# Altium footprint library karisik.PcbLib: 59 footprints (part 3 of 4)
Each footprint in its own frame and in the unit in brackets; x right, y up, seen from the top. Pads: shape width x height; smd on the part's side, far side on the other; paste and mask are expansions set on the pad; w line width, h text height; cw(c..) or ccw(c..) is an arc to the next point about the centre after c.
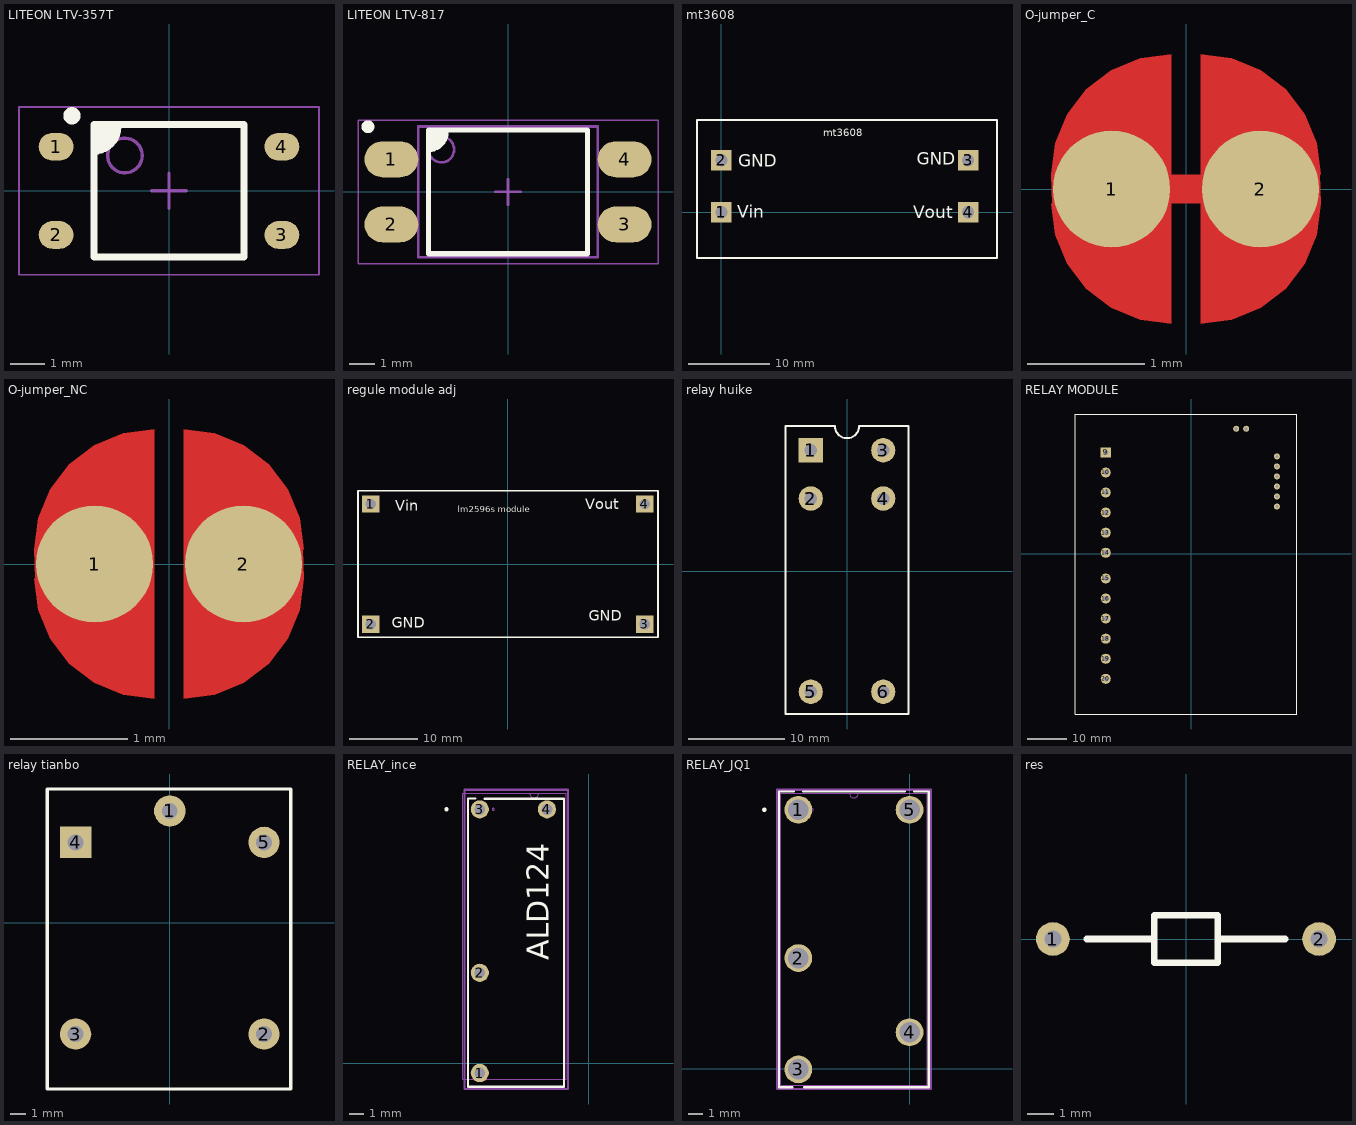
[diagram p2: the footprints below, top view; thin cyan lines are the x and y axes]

## LITEON LTV-357T [mm] "SOP, 4-Leads, Body 3.85x4.4mm, Pitch 2.54mm, IPC Medium Density"
height 2.1
pads (4):
  oval 1x0.8 smd: 1(-3.25,1.27) 2(-3.25,-1.27) 3(3.25,-1.27) 4(3.25,1.27)
Top Overlay:
  circle w0.25: c-2.794,2.159 r0.125
  region: -2.159,1.905 -1.472,1.905 -1.472,1.524 -1.853,1.143 -2.159,1.143
  lines w0.2: -2.159,1.143 ccw(c-2.159,1.83) -1.472,1.83 ; -2.159,-1.905 2.159,-1.905 2.159,1.905 -2.159,1.905 -2.159,-1.905
Mechanical 13:
  circle w0.1: c-1.27,1.016 r0.5
  lines w0.1: -2.159,-1.905 2.159,-1.905 2.159,1.905 -2.159,1.905 -2.159,-1.905
Mechanical 15:
  lines w0.05: -4.318,-2.413 4.318,-2.413 4.318,2.413 -4.318,2.413 -4.318,-2.413
  lines w0.1: -0.5,0 0.5,0 ; 0,-0.5 0,0.5
3D body: height 2.1, standoff 0, extent -3.514,-1.925 3.514,1.925

## LITEON LTV-817 [mm] "SOP, 4-Leads, Body 4.60x6.50mm, Pitch 2.54mm, IPC Medium Density"
height 4.35
pads (4):
  oval 2.1x1.4 smd: 1(-4.55,1.27) 2(-4.55,-1.27) 3(4.55,-1.27) 4(4.55,1.27)
Top Overlay:
  circle w0.25: c-5.461,2.54 r0.125
  region: -3.1,2.413 -2.413,2.413 -2.413,2.032 -2.794,1.651 -3.1,1.651
  lines w0.2: -3.1,1.651 ccw(c-3.1,2.338) -2.413,2.338 ; -3.1,-2.413 3.1,-2.413 3.1,2.413 -3.1,2.413 -3.1,-2.413
Mechanical 13:
  circle w0.1: c-2.6,1.65 r0.5
  lines w0.1: -3.5,-2.55 3.5,-2.55 3.5,2.55 -3.5,2.55 -3.5,-2.55
Mechanical 15:
  lines w0.05: -5.85,-2.8 5.85,-2.8 5.85,2.8 -5.85,2.8 -5.85,-2.8
  lines w0.1: -0.5,0 0.5,0 ; 0,-0.5 0,0.5
3D body: height 3.85, standoff 0, extent -5.098,-2.3 5.098,2.3

## mt3608 [mil] "ayarlý regulatör"
height 400
pads (4):
  rect 100x100 hole 60: 1(0,0) 2(0,253) 3(1201,253) 4(1201,0)
Top Overlay:
  lines w10: 1339,450 -119,450 -119,-224 1342,-224 1342,449
  text "Vout" at 934,-29 h60
  text "GND" at 951,231 h60
  text "GND" at 83,221 h60
  text "Vin" at 77,-26 h60
  text "mt3608" at 497,358 h60

## O-jumper_C [mm]
pads (2):
  round 1 smd paste-2: 1(-0.635,0) 2(0.635,0)
Top Layer:
  region: -0.127,-1.152 -0.392,-1.117 -0.639,-1.014 -0.852,-0.852 -1.014,-0.639 -1.117,-0.392 -1.152,-0.127 -1.143,-0.127 -1.152,0.127 -1.117,0.392 -1.014,0.639 -0.852,0.852 -0.639,1.014 -0.392,1.117 -0.127,1.152 -0.127,1.143
  region: 0.127,1.152 0.392,1.117 0.639,1.014 0.852,0.852 1.014,0.639 1.117,0.392 1.152,0.127 1.143,0.127 1.152,-0.127 1.117,-0.392 1.014,-0.639 0.852,-0.852 0.639,-1.014 0.392,-1.117 0.127,-1.152 0.127,-1.143
  lines w0.25: -0.635,0 0.635,0
Top Solder:
  region: 0,1.281 0.332,1.237 0.64,1.109 0.906,0.906 1.109,0.64 1.237,0.332 1.281,0 1.237,-0.332 1.109,-0.64 0.906,-0.906 0.64,-1.109 0.332,-1.237 0,-1.281 -0.332,-1.237 -0.64,-1.109 -0.906,-0.906 -1.109,-0.64 -1.237,-0.332 -1.281,0 -1.237,0.332 -1.109,0.64 -0.906,0.906 -0.64,1.109 -0.332,1.237

## O-jumper_NC [mm]
pads (2):
  round 1 smd paste-2: 1(-0.635,0) 2(0.635,0)
Top Layer:
  region: -0.127,-1.152 -0.392,-1.117 -0.639,-1.014 -0.852,-0.852 -1.014,-0.639 -1.117,-0.392 -1.152,-0.127 -1.143,-0.127 -1.152,0.127 -1.117,0.392 -1.014,0.639 -0.852,0.852 -0.639,1.014 -0.392,1.117 -0.127,1.152 -0.127,1.143
  region: 0.127,1.152 0.392,1.117 0.639,1.014 0.852,0.852 1.014,0.639 1.117,0.392 1.152,0.127 1.143,0.127 1.152,-0.127 1.117,-0.392 1.014,-0.639 0.852,-0.852 0.639,-1.014 0.392,-1.117 0.127,-1.152 0.127,-1.143
Top Solder:
  region: 0,1.281 0.332,1.237 0.64,1.109 0.906,0.906 1.109,0.64 1.237,0.332 1.281,0 1.237,-0.332 1.109,-0.64 0.906,-0.906 0.64,-1.109 0.332,-1.237 0,-1.281 -0.332,-1.237 -0.64,-1.109 -0.906,-0.906 -1.109,-0.64 -1.237,-0.332 -1.281,0 -1.237,0.332 -1.109,0.64 -0.906,0.906 -0.64,1.109 -0.332,1.237

## PCBComponent_1 [mil]

## PCBComponent_1 - duplicate [mil]

## PCBComponent_1 - duplicate1 [mil]

## PCBComponent_1 - duplicate2 [mil]

## regule module adj [mil] "ayarlý regulatör"
height 400
pads (4):
  rect 100x100 hole 60: 1(-785,345) 2(-785,-345) 3(785,-345) 4(785,345)
Top Overlay:
  lines w10: -858,-419 -858,421 862,421 862,-419 357,-419 -493,-419 -858,-419
  text "Vout" at 445,315 h60
  text "GND" at 465,-325 h60
  text "GND" at -665,-365 h60
  text "Vin" at -645,305 h60
  text "lm2596s module" at -285,285 h60

## relay huike [mm]
pads (6):
  rect 2.5x2.54 hole 1.3: 1(-3.75,12.5)
  oval 2.5x2.54 hole 1.3: 2(-3.75,7.5) 3(3.75,12.5) 4(3.75,7.5) 5(-3.75,-12.5) 6(3.75,-12.5)
Top Overlay:
  lines w0.2: -6.35,-14.8 -6.35,15 -1.25,15 ccw(c0,15) 1.25,15 6.35,15 6.35,-14.8 -6.35,-14.8

## RELAY MODULE [mil]
pads (20):
  round 60 hole 30: 1(852.5,470.45) 2(852.5,570.45) 3(852.5,670.45) 4(852.5,770.45) 5(852.5,870.45) 6(852.5,970.45) 7(546.5,1245.45) 8(446.5,1245.45)
  rect 100x100 hole 50: 9(-852.5,1010.45)
  round 100 hole 50: 10(-852.5,810.45) 11(-852.5,610.45) 12(-852.5,410.45) 13(-852.5,210.45) 14(-852.5,10.45) 15(-852.5,-245.45) 16(-852.5,-445.45) 17(-852.5,-645.45) 18(-852.5,-845.45) 19(-852.5,-1045.45) 20(-852.5,-1245.45)
Top Layer:
  lines w10: -854.07,608.88 -852.5,610.45 ; 546.22,1245.18 546.5,1245.45 ; 852.22,870.73 852.5,870.45
Top Overlay:
  lines w10: -1155.65,-1595.85 -1155.65,1392.34 1049.07,1392.34 1049.07,-1595.85 -1155.65,-1595.85

## relay tianbo [mm] "tianbo"
height 15.5
pads (5):
  round 2 hole 1: 1(0,7.1) 2(6,-7.1) 3(-6,-7.1) 5(6,5.1)
  rect 2x2 hole 1: 4(-6,5.1)
Top Overlay:
  lines w0.2: -7.8,-10.6 -7.8,8.5 7.7,8.5 7.7,-10.6 -7.8,-10.6

## RELAY_ince [mil]
pads (4):
  round 50 hole 30 mask+0: 1(-300,-27) 2(-300,249) 3(-300,699) 4(-115,699)
Top Overlay:
  circle w6: c-391.5,699 r3
  lines w6: -312.62,729 -332,729 -332,-65 -68,-65 -68,728 -287.38,728
  text "ALD124" at -110,284 h60
Mechanical 13:
  circle w0: c-262.5,699 r3
  lines w0: -162,743 ccw(c-150,743) -138,743
  lines w1: -347,-44 -347,743 -62,743 -62,-44 -347,-44
  text "*" at -312.5,715.67 h50
Mechanical 15:
  lines w6: -342,-71 -57,-71 -57,753 -342,753 -342,-71
3D body: height 10, standoff 0, extent 0,0 10,10

## RELAY_JQ1 [mil]
pads (5):
  round 75 hole 55 mask+0: 1(-300,699) 2(-300,299) 3(-300,-1) 4(0,99) 5(0,699)
Top Overlay:
  circle w6: c-391.5,699 r3
  lines w6: -316.01,-49 -352,-49 -352,748 -312.62,748 ; -287.38,748 -12.62,748 ; -283.99,-49 52,-49 52,748 12.62,748
Mechanical 13:
  circle w0: c-262.5,699 r3
  lines w0: -162,743 ccw(c-150,743) -138,743
  lines w1: -347,-44 47,-44 47,743 -347,743 -347,-44
  text "*" at -312.5,715.67 h50
Mechanical 15:
  lines w6: -357,-54 -357,753 57,753 57,-54 -357,-54
3D body: height 10, standoff 0, extent 0,0 10,10

## res [mil]
pads (2):
  round 50 hole 25: 1(-197,0) 2(197,0)
Top Overlay:
  lines w10: -147,0 -47,0 ; 47,0 147,0 ; -47,0 -47,-35 47,-35 47,35 -47,35 -47,0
